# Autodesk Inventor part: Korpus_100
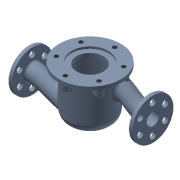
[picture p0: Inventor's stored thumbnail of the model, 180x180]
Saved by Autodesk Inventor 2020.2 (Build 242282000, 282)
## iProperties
Created: 2010-12
Part Number: Korpus_100
Document SubType Name: Modeling
Designer: F.Stasiak
Density: 1 g/cm^3
Material: Domyślny
Appearance: Stalowoniebieska - jasna
Manager: www.cadconsulting.pl
Company: Fabian Stasiak CAD Consulting
Author: F.Stasiak
Subject: Zbiór ćwiczeń. Autodesk Inventor 2020. Kurs podstawowy
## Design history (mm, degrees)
sketch "Szkic2"
  geometry: L1 (0, 0)-(0, 120); L2 (0, 120)-(55, 120); L3 (55, 120)-(55, 25); L4 (30, 0)-(0, 0); L5 (32.5, 120)-(32.5, 105); L6 (47.5, 55)-(0, 55); L7 (37.5, 55)-(37.5, 8); L8 (37.5, 8)-(0, 8); L9 (32.5, 105)-(47.5, 105); L10 (47.5, 105)-(47.5, 55); A1 r 25 centre (30, 25) between (30, 0) and (55, 25)
  constraints: 20 end point, 7 perpendicular, 4 point on line, 2 parallel, 2 point on circle, 1 centre point, 1 tangent, 1 vertical
  dimensions: "d3" = 120 distance of L1.start L1.end; "d5" = 95 distance of L2.end L3.end; "d7" = 15 distance of L5.start L5.end; "d8" = 110 diameter of L3 L1; "d9" = 65 diameter of L5 L1; "d10" = 95 diameter of L10 L1; "d11" = 65 distance between parallel lines of L6 L2; "d12" = 75 diameter of L7 L1; "d13" = 60 diameter of L4.start L1; "d14" = 8 distance between parallel lines of L8 L4
revolve "Obrót1" stored, may be unused: angle "d15" = 90 deg
node "Płaszczyzna konstrukcyjna1"
node "Płaszczyzna konstrukcyjna2"
sketch "Szkic3"
  geometry: C1 r 50 at (25, 50); 1 further point
  constraints: 1 centre point
  dimensions: "d25" = 100 diameter of C1; "d69" = 50 vertical distance of C1.centre point (0, 0); "d70" = 25 horizontal distance of C1.centre point (0, 0)
extrude "Wyciągnięcie proste2" join sketch "Szkic3" distance "d28" = 8; taper "d29" = 0 deg
node "Płaszczyzna konstrukcyjna3"
sketch "Szkic4"
  geometry: C1 r 20 at (25, 85); 1 further point
  constraints: 1 centre point
  dimensions: "d31" = 40 diameter of C1; "d71" = 25 horizontal distance of C1.centre point (0, 0); "d72" = 85 vertical distance of C1.centre point (0, 0)
sketch "Szkic5"
  geometry: C1 r 20 at (0, 0); 2 further points
  constraints: 1 centre point, 3 other
  dimensions: "d33" = 40 diameter of C1
feature "Wyciągnięcie złożone1" sketch "Szkic4", "Szkic5" dims "d34" = 110, "d35" = 90 deg, "d36" = 110, "d37" = 90 deg
node "Płaszczyzna konstrukcyjna4"
sketch "Szkic7"
  geometry: 1 further point
sketch "Szkic8"
  geometry: C1 r 15 at (25, 85); 2 further points
  constraints: 1 centre point, 1 coincident
  dimensions: "d41" = 30 diameter of C1
sketch "Szkic9"
  geometry: C1 r 15 at (0, 0); 2 further points
  constraints: 1 centre point, 1 coincident, 1 other
  dimensions: "d42" = 30 diameter of C1
feature "Wyciągnięcie złożone2" sketch "Szkic9" dims "d43" = 160, "d44" = 90 deg, "d45" = 160, "d46" = 90 deg
sketch "Szkic10"
  geometry: C1 r 50.158 at (-20, 50); 2 further points
  constraints: 1 centre point, 1 other
  dimensions: "d73" = 20 horizontal distance of point (0, 0) C1.centre; "d74" = 50 vertical distance of C1.centre point (0, 0)
extrude "Wyciągnięcie proste3" join sketch "Szkic10" distance "d47" = 8; taper "d48" = 0 deg
node "Płaszczyzna konstrukcyjna6"
sketch "Szkic11"
  geometry: C1 r 20 at (-20, 25); 1 further point
  constraints: 1 centre point
  dimensions: "d50" = 40 diameter of C1; "d76" = 25 vertical distance of C1.centre point (0, 0); "d77" = 20 horizontal distance of point (0, 0) C1.centre
sketch "Szkic12"
  geometry: C1 r 20 at (0, -45); C2 r 50.158 at (0, -45) reference; 1 further point
  constraints: 1 centre point, 1 coincident
  dimensions: "d52" = 40 diameter of C1
feature "Wyciągnięcie złożone3" sketch "Szkic11", "Szkic12" dims "d53" = 100, "d54" = 90 deg, "d55" = 100, "d56" = 90 deg
node "Płaszczyzna konstrukcyjna7"
revolve "Obrót2" stored, may be unused: angle "d78" = 90 deg
sketch "Szkic13"
  geometry: C1 r 15 at (-20, 27); 1 further point
  constraints: 1 centre point
  dimensions: "d58" = 30 diameter of C1; "d81" = 27 vertical distance of C1.centre point (0, 0); "d82" = 20 horizontal distance of C1.centre point (0, 0)
feature "Wyciągnięcie złożone4" sketch "Szkic13" dims "d60" = 140, "d61" = 90 deg, "d62" = 140, "d63" = 90 deg
fillet "Zaokrąglenie4" dims "d64" = 5
fillet "Zaokrąglenie5" dims "d65" = 10
fillet "Zaokrąglenie6" dims "d83" = 10
sketch "Szkic15"
  geometry: C1 r 55 at (0, 0) reference; C2 r 75 at (0, 0)
  constraints: 1 centre point, 1 coincident
  dimensions: "d84" = 150 diameter of C2
extrude "Wyciągnięcie proste5" join sketch "Szkic15" distance "d85" = 8; taper "d86" = 0 deg
sketch "Szkic16"
  geometry: C1 r 50 at (0, 0) reference; 3 further points
  dimensions: "d87" = 35 distance of C1.centre point (-35, 0)
hole "Otwór1" sketch "Szkic16" at (-35, 0) diameter "d88" = 15; stored, may be unused: countersink angle "d92" = 90 deg, drill point angle "d94" = 118 deg; dims "d89" = 6, "d90" = 4, "d91" = 2, "d93" = 8
pattern_circular "Szyk kołowy1" dims angle "d96" = 360 deg
sketch "Szkic17"
  geometry: C1 r 50.158 at (0, 0) reference; 3 further points
  dimensions: "d98" = 35 distance of C1.centre point (35, 0)
hole "Otwór2" sketch "Szkic17" at (35, 0) diameter "d99" = 15; stored, may be unused: countersink angle "d103" = 90 deg, drill point angle "d105" = 118 deg; dims "d100" = 6, "d101" = 4, "d102" = 2, "d104" = 8
pattern_circular "Szyk kołowy2" dims angle "d107" = 360 deg
fillet "Zaokrąglenie7" dims "d111" = 8
sketch "Szkic18" dims "d113" = 120
  geometry: C1 r 10 at (0, 60); A1 r 55 centre (0, 0) between (-35.295, -42.181) and (-54.56, 6.946) reference; 2 further points
  constraints: 1 centre point, 1 coincident, 1 point on circle, 1 vertical alignment, 2 other
  dimensions: "d114" = 20 diameter of C1
extrude "Wyciągnięcie proste6" join sketch "Szkic18" distance "d115" = 30; taper "d116" = 0 deg
fillet "Zaokrąglenie8" dims "d117" = 4
fillet "Zaokrąglenie9" dims "d118" = 4
hole "Otwór3" sketch "Szkic18" diameter "d119" = 10.106; stored, may be unused: countersink angle "d123" = 90 deg, drill point angle "d125" = 118 deg; dims "d120" = 20, "d121" = 4, "d122" = 2, "d124" = 25
sketch "Szkic19"
  geometry: C1 r 32.5 at (0, 0) reference; C2 r 45 at (0, 0)
  constraints: 1 centre point, 1 coincident
  dimensions: "d126" = 90 diameter of C2
extrude "Wyciągnięcie proste7" cut sketch "Szkic19" distance "d127" = 5; taper "d128" = 0 deg
pattern_circular "Szyk kołowy3" dims angle "d130" = 360 deg
fillet "Zaokrąglenie10" dims "d132" = 4
fillet "Zaokrąglenie11" dims "d133" = 4
node "Bryła2"
sketch "Szkic14"
  geometry: C1 r 15 at (0, -45); C2 r 50.158 at (0, -45) reference; 1 further point
  constraints: 1 centre point
  dimensions: "d59" = 30 diameter of C1; "d80" = 0 distance of C2.centre C1.centre
other parameters: "d40" = -8, "d57" = 8
